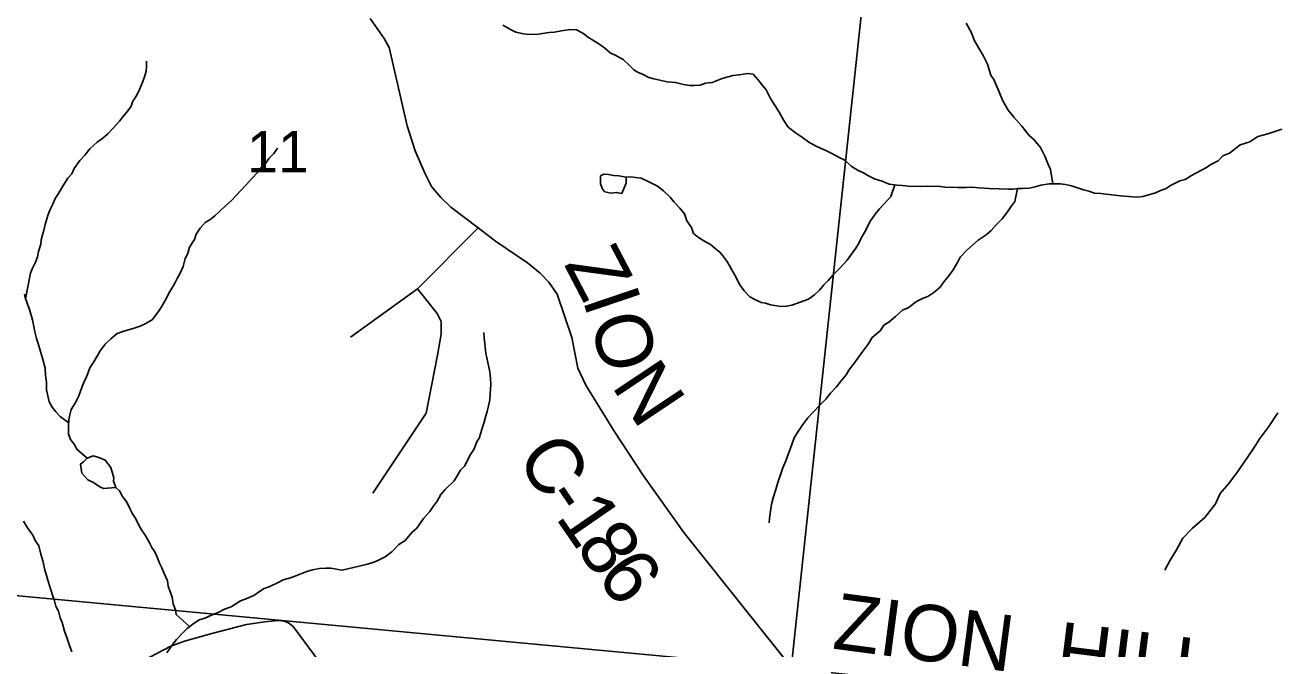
# Model space of a CAD drawing. Extents: x 0 to 34, y 0 to 22.
# Drawn here: x 3.401 to 4.664, y 15.353 to 15.983 of the extents above; entities that cross this region are included whole.
import ezdxf

# ---------------------------------------------------------------- set-up
doc = ezdxf.new("R2010")
doc.units = 0
for name, color, linetype in [('GM_X_County_Road', 7, 'Continuous'), ('GM_X_County_Road_Text', 7, 'Continuous'), ('GM_X_Minor_Lake', 7, 'Continuous'), ('GM_X_Minor_River', 7, 'Continuous'), ('GM_X_Section', 7, 'Continuous'), ('GM_X_Section_Text', 7, 'Continuous'), ('GM_X_Township_Road', 7, 'Continuous')]:
    doc.layers.add(name, color=color, linetype=linetype)

msp = doc.modelspace()

# ---------------------------------------------------------------- linework, layer by layer
at = {"layer": 'GM_X_County_Road'}
for points in [[(4.1748, 15.3344), (4.0662, 15.4704), (4.0256, 15.5277), (3.996, 15.5729), (3.9673, 15.6192), (3.9594, 15.6365), (3.9534, 15.6674), (3.9383, 15.7111), (3.9299, 15.7231), (3.9214, 15.7324), (3.9084, 15.7426), (3.8763, 15.7644), (3.8587, 15.7779), (3.8313, 15.799), (3.821, 15.8087), (3.8118, 15.8196), (3.8049, 15.8331), (3.7953, 15.8557), (3.7872, 15.881), (3.7689, 15.9601), (3.7638, 15.969), (3.7499, 15.9894)], [(3.4921, 15.3261), (3.5487, 15.3559), (3.5625, 15.3607), (3.5901, 15.3685), (3.625, 15.3776), (3.6434, 15.3805), (3.6572, 15.3818), (3.663, 15.3811), (3.6675, 15.3795), (3.672, 15.3757), (3.7001, 15.338)]]:
    msp.add_lwpolyline(points, dxfattribs=at)
at = {"layer": 'GM_X_Minor_Lake'}
for points in [[(4.0079, 15.8291), (4.0007, 15.8305), (3.9954, 15.8307), (3.9904, 15.8319), (3.9855, 15.8321), (3.982, 15.8303), (3.9822, 15.8223), (3.9843, 15.8169), (3.9866, 15.8142), (3.9926, 15.8129), (3.9979, 15.8135), (4.0036, 15.8126)], [(4.0036, 15.8126), (4.006, 15.8182), (4.0081, 15.8231), (4.0079, 15.8291)], [(3.4932, 15.5158), (3.4906, 15.5223), (3.4911, 15.5257), (3.488, 15.536), (3.4824, 15.5434), (3.4761, 15.5462), (3.4704, 15.5479), (3.4643, 15.5454), (3.4604, 15.5417), (3.4576, 15.5395), (3.4589, 15.5304), (3.4648, 15.5237), (3.4705, 15.5209), (3.4768, 15.5166), (3.4806, 15.515)], [(3.4806, 15.515), (3.4932, 15.5158)]]:
    msp.add_lwpolyline(points, dxfattribs=at)
at = {"layer": 'GM_X_Minor_River'}
for points in [[(4.3745, 15.8176), (4.3692, 15.8181), (4.3639, 15.8183), (4.3567, 15.8189), (4.3514, 15.8187), (4.3426, 15.8187), (4.3301, 15.8191), (4.3252, 15.8197), (4.3123, 15.8201), (4.3047, 15.8196), (4.2926, 15.82), (4.2869, 15.8206), (4.2816, 15.8212), (4.2733, 15.8222), (4.2654, 15.8255), (4.2594, 15.8272), (4.252, 15.8309), (4.2475, 15.8334), (4.2422, 15.8358), (4.2352, 15.8402), (4.2286, 15.8462), (4.223, 15.849), (4.2155, 15.8531), (4.2095, 15.8559), (4.2047, 15.858), (4.1991, 15.8609), (4.1924, 15.8645), (4.1861, 15.8693), (4.179, 15.8737), (4.1716, 15.8797), (4.1673, 15.8863), (4.1623, 15.8948), (4.1583, 15.901), (4.1536, 15.9084), (4.1494, 15.9173), (4.1446, 15.9231), (4.141, 15.9278), (4.1362, 15.9329), (4.131, 15.9339), (4.1222, 15.9323), (4.1157, 15.9317), (4.1111, 15.9304), (4.105, 15.9287), (4.095, 15.9248), (4.0881, 15.9239), (4.0827, 15.9219), (4.0766, 15.9217), (4.0721, 15.9215), (4.066, 15.9228), (4.0577, 15.9246), (4.0494, 15.9253), (4.0419, 15.9271), (4.0359, 15.9284), (4.031, 15.9297), (4.0246, 15.933), (4.0201, 15.9347), (4.0157, 15.9375), (4.0113, 15.9418), (4.005, 15.9477), (3.9976, 15.9518), (3.992, 15.9546), (3.9864, 15.9594), (3.9816, 15.9629), (3.9745, 15.9674), (3.9701, 15.9702), (3.9645, 15.9746), (3.9578, 15.9778), (3.9521, 15.978), (3.9449, 15.9771), (3.9353, 15.9756), (3.9304, 15.975), (3.9193, 15.9735), (3.9098, 15.973), (3.9045, 15.9736), (3.8966, 15.9754), (3.8907, 15.9786), (3.8836, 15.9826)], [(4.4386, 15.8224), (4.4363, 15.8367), (4.4331, 15.8437), (4.431, 15.8498), (4.426, 15.8591), (4.4199, 15.8669), (4.4147, 15.8713), (4.4074, 15.8806), (4.3997, 15.8893), (4.3935, 15.8967), (4.3907, 15.9013), (4.3878, 15.9068), (4.384, 15.916), (4.379, 15.9276), (4.3762, 15.9322), (4.3727, 15.943), (4.3688, 15.9511), (4.366, 15.9558), (4.3595, 15.9666), (4.3564, 15.9747), (4.351, 15.9844)], [(3.402, 15.7062), (3.4069, 15.7321), (3.4089, 15.7374), (3.4122, 15.7433), (3.4139, 15.7486), (3.4152, 15.7542), (3.4174, 15.7614), (3.4179, 15.7659), (3.4192, 15.7708), (3.4205, 15.7753), (3.4218, 15.7813), (3.4231, 15.7859), (3.4248, 15.7915), (3.4269, 15.7964), (3.4294, 15.802), (3.4318, 15.8076), (3.4351, 15.8128), (3.4391, 15.8191), (3.4447, 15.828), (3.4486, 15.8325), (3.4511, 15.8377), (3.4567, 15.8459), (3.4618, 15.8514), (3.467, 15.8577), (3.4744, 15.8646), (3.4799, 15.8686), (3.485, 15.873), (3.4905, 15.8785), (3.4968, 15.8855), (3.5016, 15.8918), (3.5051, 15.8962), (3.5087, 15.9007), (3.51, 15.9052), (3.5144, 15.9119), (3.5169, 15.9175), (3.5202, 15.9257), (3.5223, 15.9313), (3.5236, 15.9362), (3.5241, 15.9408), (3.5239, 15.9461)], [(4.6697, 15.8777), (4.6554, 15.8728), (4.6455, 15.8701), (4.6373, 15.8647), (4.6277, 15.8616), (4.6168, 15.8533), (4.6103, 15.8508), (4.6055, 15.8457), (4.5986, 15.8421), (4.5931, 15.8385), (4.5881, 15.836), (4.5784, 15.8307), (4.5722, 15.8267), (4.5669, 15.8254), (4.558, 15.8211), (4.5522, 15.8175), (4.5472, 15.8158), (4.5422, 15.8133), (4.5295, 15.8096), (4.5245, 15.809), (4.5189, 15.8092), (4.5068, 15.8103), (4.5011, 15.8109), (4.4924, 15.812), (4.4871, 15.8125), (4.4807, 15.8131), (4.475, 15.8149), (4.4697, 15.8162), (4.4634, 15.8183), (4.4574, 15.8204), (4.4513, 15.8218), (4.446, 15.8223), (4.4411, 15.8225), (4.435, 15.8223), (4.4266, 15.8211), (4.4209, 15.8194), (4.4148, 15.8181), (4.4079, 15.8176), (4.4034, 15.8177), (4.3984, 15.8171), (4.3938, 15.8169), (4.3745, 15.8176)], [(3.4642, 15.5454), (3.4539, 15.5546), (3.4511, 15.5596), (3.4474, 15.5643), (3.4454, 15.5701), (3.4452, 15.5781), (3.4458, 15.5841), (3.4468, 15.5894), (3.4481, 15.5947), (3.4521, 15.601), (3.4558, 15.6085), (3.4579, 15.6141), (3.4604, 15.6212), (3.4636, 15.6276), (3.4653, 15.6321), (3.467, 15.6366), (3.471, 15.6429), (3.4742, 15.6485), (3.4774, 15.6537), (3.4822, 15.6607), (3.4881, 15.6659), (3.4944, 15.6713), (3.5013, 15.6738), (3.5117, 15.6768), (3.5178, 15.6789), (3.5228, 15.681), (3.5298, 15.6853), (3.5361, 15.6935), (3.5393, 15.6983), (3.543, 15.7046), (3.5471, 15.7132), (3.5523, 15.7214), (3.5551, 15.727), (3.5576, 15.7315), (3.5609, 15.7389), (3.563, 15.7472), (3.5659, 15.7521), (3.5676, 15.7585), (3.5724, 15.7663), (3.5741, 15.7715), (3.5781, 15.7775), (3.5833, 15.7834), (3.5879, 15.7862), (3.593, 15.7902), (3.5977, 15.7946), (3.604, 15.8005), (3.6098, 15.8056), (3.6142, 15.8104), (3.6197, 15.8159), (3.6248, 15.8218), (3.6303, 15.8277), (3.6363, 15.8343), (3.6398, 15.8388), (3.6445, 15.8432), (3.6474, 15.848), (3.6525, 15.8531), (3.6561, 15.8583)], [(4.2793, 15.8214), (4.2751, 15.8096), (4.2676, 15.8015), (4.2637, 15.7971), (4.2593, 15.7919), (4.2538, 15.7841), (4.2496, 15.7748), (4.2456, 15.7681), (4.2428, 15.7625), (4.2399, 15.7573), (4.2344, 15.7499), (4.2312, 15.7454), (4.2241, 15.7377), (4.2166, 15.7303), (4.2119, 15.7248), (4.2075, 15.7204), (4.2032, 15.7152), (4.1981, 15.7105), (4.1919, 15.7061), (4.1872, 15.7044), (4.1811, 15.7019), (4.1753, 15.6998), (4.17, 15.6989), (4.1646, 15.6987), (4.1601, 15.6992), (4.1537, 15.7002), (4.1488, 15.7019), (4.1443, 15.7028), (4.1379, 15.7057), (4.1327, 15.7085), (4.1272, 15.7144), (4.1221, 15.7214), (4.119, 15.728), (4.1132, 15.7381), (4.1104, 15.7435), (4.1071, 15.7482), (4.1027, 15.7533), (4.0976, 15.7576), (4.0931, 15.7612), (4.0864, 15.7648), (4.0812, 15.7681), (4.0761, 15.7724), (4.074, 15.7782), (4.0693, 15.7852), (4.0669, 15.7921), (4.0621, 15.798), (4.0566, 15.8039), (4.0526, 15.8089), (4.0456, 15.8152), (4.0397, 15.82), (4.0304, 15.8249), (4.0233, 15.8282), (4.0176, 15.8288), (4.0127, 15.8293), (4.0079, 15.8291)], [(4.4029, 15.8177), (4.4002, 15.8045), (4.3963, 15.7993), (4.3927, 15.7941), (4.3875, 15.7871), (4.3816, 15.7812), (4.3765, 15.7753), (4.3714, 15.771), (4.3632, 15.7655), (4.3574, 15.7604), (4.3519, 15.7553), (4.3452, 15.7483), (4.3427, 15.7438), (4.3379, 15.7356), (4.3335, 15.7297), (4.3287, 15.7234), (4.3248, 15.7182), (4.3185, 15.7128), (4.3123, 15.7088), (4.3077, 15.7071), (4.3011, 15.7035), (4.2925, 15.6973), (4.2868, 15.6949), (4.2797, 15.6886), (4.2731, 15.6828), (4.268, 15.6799), (4.2644, 15.674), (4.2562, 15.6674), (4.2522, 15.6607), (4.2462, 15.6526), (4.2418, 15.6466), (4.2374, 15.6403), (4.2327, 15.6344), (4.2302, 15.6296), (4.2251, 15.6237), (4.2203, 15.6174), (4.2144, 15.6111), (4.2097, 15.6052), (4.2034, 15.599), (4.1967, 15.592), (4.1915, 15.5861), (4.1864, 15.5794), (4.1808, 15.5713), (4.1776, 15.5661), (4.1751, 15.5593), (4.1717, 15.5503), (4.1692, 15.5428), (4.1663, 15.5357), (4.1642, 15.5297), (4.1612, 15.521), (4.1591, 15.5139), (4.1565, 15.5056), (4.1548, 15.4992), (4.1528, 15.4849), (4.1522, 15.4803)], [(3.4456, 15.5812), (3.4372, 15.5871), (3.4324, 15.5922), (3.4288, 15.5969), (3.426, 15.6023), (3.4233, 15.6145), (3.4232, 15.6221), (3.4223, 15.6294), (3.4218, 15.6362), (3.4194, 15.6451), (3.4147, 15.6612), (3.413, 15.6662), (3.4113, 15.6731), (3.4103, 15.6784), (3.4091, 15.6853), (3.406, 15.6957), (3.4035, 15.7018), (3.4015, 15.7076), (3.4008, 15.7111)], [(3.7214, 15.4325), (3.7457, 15.4382), (3.7514, 15.4399), (3.7561, 15.4416), (3.7649, 15.4459), (3.7716, 15.4509), (3.7786, 15.4583), (3.7849, 15.4626), (3.792, 15.4707), (3.7967, 15.4748), (3.8035, 15.4848), (3.8098, 15.4918), (3.8134, 15.4966), (3.8174, 15.5022), (3.821, 15.5089), (3.8254, 15.514), (3.8344, 15.5228), (3.8408, 15.5333), (3.8452, 15.5377), (3.8504, 15.5481), (3.8545, 15.5544), (3.8574, 15.5619), (3.8602, 15.5664), (3.8628, 15.5758), (3.8649, 15.5818), (3.8666, 15.5882), (3.8679, 15.5927), (3.8693, 15.5984), (3.8706, 15.6044), (3.8708, 15.6105), (3.8715, 15.6199), (3.8713, 15.626), (3.8704, 15.6325), (3.8695, 15.6375), (3.8685, 15.6421), (3.8665, 15.6516), (3.8648, 15.6669), (3.8646, 15.6722)], [(4.6656, 15.5912), (4.6565, 15.5774), (4.6474, 15.5655), (4.641, 15.5554), (4.6311, 15.5405), (4.6244, 15.5308), (4.6157, 15.5196), (4.6075, 15.51), (4.6026, 15.4995), (4.592, 15.4857), (4.5791, 15.4747), (4.5697, 15.4647), (4.5633, 15.4531), (4.5569, 15.4426), (4.5517, 15.4325)], [(3.5675, 15.3755), (3.5541, 15.3878), (3.5532, 15.3924), (3.5511, 15.3985), (3.5498, 15.4051), (3.546, 15.4162), (3.5454, 15.4219), (3.5419, 15.4293), (3.5394, 15.435), (3.5373, 15.4397), (3.5349, 15.4458), (3.5324, 15.4509), (3.5295, 15.4555), (3.5267, 15.4609), (3.5227, 15.4679), (3.5191, 15.4733), (3.5162, 15.478), (3.5134, 15.4842), (3.5098, 15.4892), (3.5073, 15.4947), (3.5041, 15.5012), (3.4997, 15.5067), (3.4969, 15.5125), (3.4932, 15.5158)], [(3.4488, 15.35), (3.4464, 15.3566), (3.444, 15.3635), (3.4412, 15.3708), (3.4388, 15.3796), (3.4371, 15.3843), (3.4354, 15.3912), (3.4326, 15.3962), (3.4312, 15.4016), (3.4295, 15.4062), (3.4274, 15.4127), (3.4254, 15.4192), (3.4213, 15.433), (3.4193, 15.4419), (3.4173, 15.4488), (3.4153, 15.4572), (3.4117, 15.4626), (3.4092, 15.468), (3.4041, 15.4754), (3.3998, 15.482)], [(3.6253, 15.404), (3.6322, 15.4071), (3.6381, 15.4111), (3.6427, 15.414), (3.6485, 15.4161), (3.657, 15.42), (3.662, 15.4228), (3.6693, 15.4248), (3.6747, 15.4269), (3.6816, 15.4294), (3.687, 15.4315), (3.6916, 15.4328), (3.6985, 15.4341), (3.7049, 15.4346), (3.7099, 15.4345), (3.7212, 15.4325), (3.7214, 15.4325)], [(3.5445, 15.349), (3.5496, 15.3564), (3.5544, 15.3627), (3.5599, 15.3686), (3.565, 15.3738), (3.5709, 15.3781), (3.5771, 15.3825), (3.5829, 15.3842), (3.5902, 15.3873), (3.5963, 15.3898), (3.6029, 15.3933), (3.6094, 15.3954), (3.6188, 15.4015), (3.6253, 15.404)]]:
    msp.add_lwpolyline(points, dxfattribs=at)
at = {"layer": 'GM_X_Section'}
for points in [[(3.2644, 16.338), (3.276, 16.3476), (3.3136, 16.3694), (3.3687, 16.3893), (4.2789, 16.3058), (4.1746, 15.3336), (3.1681, 15.4277)], [(5.2813, 16.2088), (5.1838, 15.2208), (4.1746, 15.3336), (4.2789, 16.3058)], [(4.1746, 15.3336), (4.0766, 14.3377), (3.0761, 14.4328), (3.1681, 15.4277)]]:
    msp.add_lwpolyline(points, close=True, dxfattribs=at)
at = {"layer": 'GM_X_Township_Road'}
for points in [[(3.73, 15.6676), (3.7975, 15.7163), (3.8587, 15.7779)], [(3.7523, 15.5103), (3.8061, 15.591), (3.8178, 15.6494), (3.8214, 15.6707), (3.8214, 15.6834), (3.8173, 15.6915), (3.8107, 15.7001), (3.8046, 15.7077), (3.7975, 15.7163)]]:
    msp.add_lwpolyline(points, dxfattribs=at)

# ---------------------------------------------------------------- texts
at = {"layer": 'GM_X_County_Road_Text'}
for s, height, rotation, p in [('Z', 0.0568, 297.601, (3.9448, 15.7413)), ('I', 0.0568, 288.6966, (3.9636, 15.7058)), ('O', 0.0568, 285.6259, (3.9709, 15.6845)), ('N', 0.0568, 303.7444, (3.9925, 15.6186)), ('C', 0.0568, 302.0637, (3.8965, 15.5469)), ('-', 0.0568, 304.3812, (3.9227, 15.5052)), ('1', 0.0568, 304.6275, (3.936, 15.4858)), ('8', 0.0568, 304.8021, (3.956, 15.4568)), ('6', 0.0568, 306.4783, (3.977, 15.4266)), ('ZION', 0.05682, 352.4824, (4.2152, 15.3535)), ('HILL', 0.05682, 352.8364, (4.4396, 15.3243))]:
    msp.add_text(s, height=height, rotation=rotation, dxfattribs=at).set_placement(p)
at = {"layer": 'GM_X_Section_Text'}
msp.add_text('11', height=0.04186, rotation=0, dxfattribs=at).set_placement((3.6256, 15.8339))

doc.saveas('drawing.dxf')
